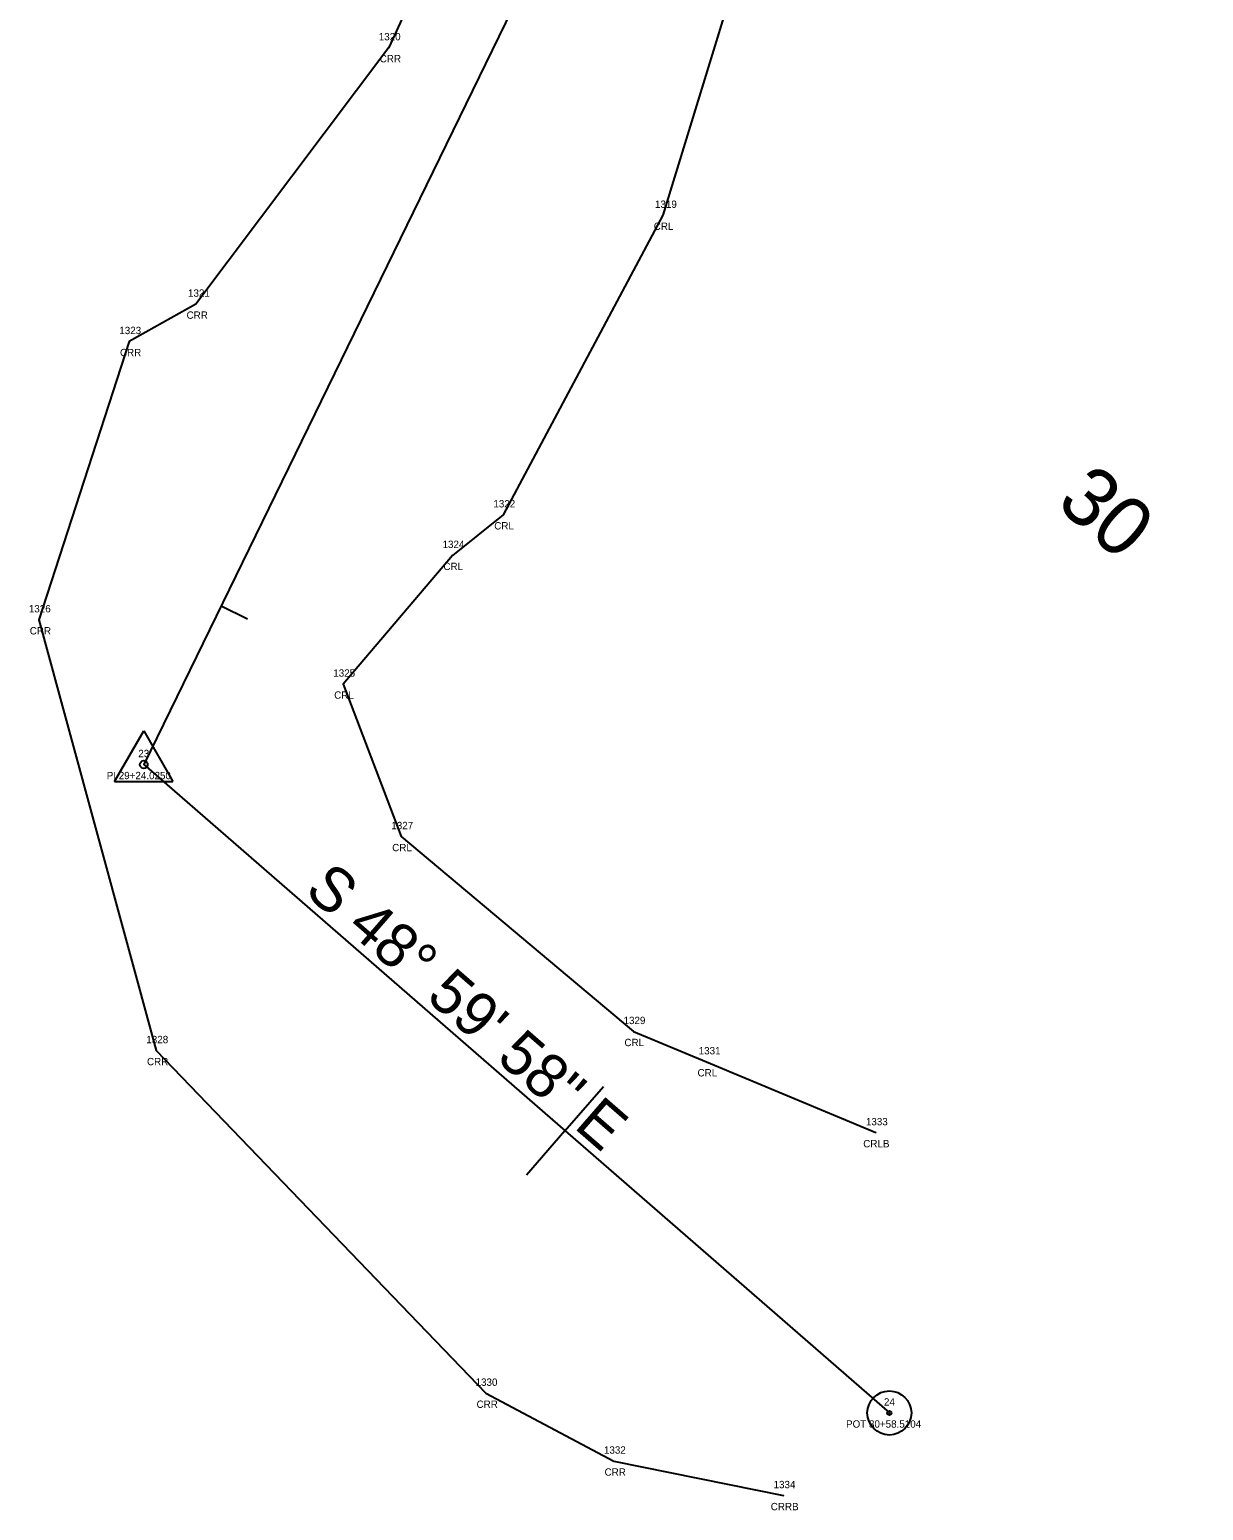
# Model space of a CAD drawing. Extents: x 1964982 to 1970527, y 1116335 to 1119906.
# Drawn here: x 1967713.8 to 1967873.6, y 1117452.2 to 1117653.6 of the extents above; entities that cross this region are included whole.
import ezdxf

# ---------------------------------------------------------------- set-up
doc = ezdxf.new("R2010")
doc.units = 0
for name, color, linetype in [('RD_EX_H2O', 7, 'Continuous'), ('RD_EX_H2O_txCode', 7, 'Continuous'), ('RD_HC_CL', 7, 'Continuous'), ('RD_HC_Data', 7, 'Continuous'), ('RD_HC_Data_Tic', 7, 'Continuous'), ('RD_HC_TX_Sta50', 7, 'Continuous'), ('RD_HC_txCode', 7, 'Continuous'), ('RD_SMD_Locator', 7, 'Continuous')]:
    doc.layers.add(name, color=color, linetype=linetype)

msp = doc.modelspace()

# ---------------------------------------------------------------- linework, layer by layer
at = {"layer": 'RD_EX_H2O'}
for points in [[(1967794.3, 1117875.45), (1967796.63, 1117853.43), (1967809.67, 1117835.4), (1967828.83, 1117808.28), (1967805.08, 1117754.56), (1967786.33, 1117708.04), (1967780.19, 1117689.35), (1967762.68, 1117651.19), (1967736.39, 1117616.3), (1967727.33, 1117611.21), (1967715.04, 1117573.35), (1967731.01, 1117514.73), (1967775.86, 1117468.11), (1967793.29, 1117458.88), (1967816.39, 1117454.18)], [(1967873.55, 1117813.3), (1967873.54, 1117810.73), (1967868.98, 1117791.48), (1967856.29, 1117756.05), (1967834.78, 1117721.72), (1967815.36, 1117678.52), (1967799.96, 1117628.39), (1967778.25, 1117587.63), (1967771.33, 1117582.11), (1967756.46, 1117564.6), (1967764.36, 1117543.85), (1967795.97, 1117517.33), (1967805.92, 1117513.21), (1967828.95, 1117503.56)]]:
    msp.add_lwpolyline(points, dxfattribs=at)
at = {"layer": 'RD_HC_CL'}
for p, q in [((1967849.81, 1117800.6), (1967729.31, 1117553.65)), ((1967729.31, 1117553.65), (1967830.8, 1117465.42))]:
    msp.add_line(p, q, dxfattribs=at)
at = {"layer": 'RD_HC_Data'}
for p, q in [((1967725.33, 1117551.36), (1967729.31, 1117558.24)), ((1967729.31, 1117558.24), (1967733.28, 1117551.36)), ((1967725.33, 1117551.36), (1967733.28, 1117551.36))]:
    msp.add_line(p, q, dxfattribs=at)
for centre, radius in [((1967729.31, 1117553.65), 0.529), ((1967830.8, 1117465.42), 3), ((1967830.8, 1117465.42), 0.282)]:
    msp.add_circle(centre, radius, dxfattribs=at)
at = {"layer": 'RD_HC_Data_Tic'}
for p, q in [((1967739.84, 1117575.25), (1967743.44, 1117573.49)), ((1967786.64, 1117503.81), (1967791.89, 1117509.85)), ((1967786.64, 1117503.81), (1967781.4, 1117497.77))]:
    msp.add_line(p, q, dxfattribs=at)
at = {"layer": 'RD_SMD_Locator'}
for centre in [(1967762.68, 1117651.19), (1967799.96, 1117628.39), (1967736.39, 1117616.3), (1967727.33, 1117611.21), (1967778.25, 1117587.63), (1967771.33, 1117582.11), (1967715.04, 1117573.35), (1967756.46, 1117564.6), (1967729.31, 1117553.65), (1967764.36, 1117543.85), (1967795.97, 1117517.33), (1967731.01, 1117514.73), (1967805.92, 1117513.21), (1967828.95, 1117503.56), (1967775.86, 1117468.11), (1967830.8, 1117465.42), (1967793.29, 1117458.88), (1967816.39, 1117454.18)]:
    msp.add_circle(centre, 0.001, dxfattribs=at)

# ---------------------------------------------------------------- texts
at = {"layer": 'RD_EX_H2O_txCode'}
for s, p in [('1320', (1967761.3, 1117652.19)), ('CRR', (1967761.43, 1117649.19)), ('1319', (1967798.9, 1117629.39)), ('CRL', (1967798.73, 1117626.39)), ('1321', (1967735.33, 1117617.3)), ('CRR', (1967735.14, 1117614.3)), ('1323', (1967725.98, 1117612.21)), ('CRR', (1967726.07, 1117609.21)), ('1322', (1967776.9, 1117588.63)), ('CRL', (1967777.02, 1117585.63)), ('1324', (1967769.98, 1117583.11)), ('CRL', (1967770.1, 1117580.11)), ('1326', (1967713.67, 1117574.35)), ('CRR', (1967713.79, 1117571.35)), ('1325', (1967755.11, 1117565.6)), ('CRL', (1967755.23, 1117562.6)), ('1327', (1967763.01, 1117544.85)), ('CRL', (1967763.13, 1117541.85)), ('1329', (1967794.62, 1117518.33)), ('1328', (1967729.66, 1117515.73)), ('CRL', (1967794.74, 1117515.33)), ('1331', (1967804.85, 1117514.21)), ('CRR', (1967729.75, 1117512.73)), ('CRL', (1967804.69, 1117511.21)), ('1333', (1967827.61, 1117504.56)), ('CRLB', (1967827.25, 1117501.56)), ('1330', (1967774.48, 1117469.11)), ('CRR', (1967774.61, 1117466.11)), ('1332', (1967791.95, 1117459.88)), ('CRR', (1967792.04, 1117456.88)), ('1334', (1967815.04, 1117455.18)), ('CRRB', (1967814.66, 1117452.18))]:
    msp.add_text(s, height=1, dxfattribs=at).set_placement(p)
at = {"layer": 'RD_HC_Data'}
msp.add_text('S 48° 59\' 58" E', height=6, rotation=318.9993, dxfattribs=at).set_placement((1967751.02, 1117536.19))
at = {"layer": 'RD_HC_TX_Sta50'}
msp.add_text('30', height=8, rotation=318.9993, dxfattribs=at).set_placement((1967853.31, 1117588.96))
at = {"layer": 'RD_HC_txCode'}
for s, p in [('23', (1967728.57, 1117554.65)), ('PI 29+24.0250', (1967724.27, 1117551.65)), ('24', (1967830.07, 1117466.42)), ('POT 30+58.5104', (1967824.91, 1117463.42))]:
    msp.add_text(s, height=1, dxfattribs=at).set_placement(p)

doc.saveas('drawing.dxf')
